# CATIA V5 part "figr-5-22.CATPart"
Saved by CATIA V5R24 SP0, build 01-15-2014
Part number: Part1
Bounding box of the stored display mesh (mm): x -50 to 50, y 0 to 90.129, z 0 to 181.346
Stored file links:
  D:\KAVITA\CATIA V5-6R2014 Project_ Kavita\CATIA V5-6R2014_partfiles\Partfiles\c05_catia_v5-6r2014_prt\figr-5-22.CATPart
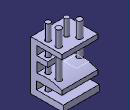
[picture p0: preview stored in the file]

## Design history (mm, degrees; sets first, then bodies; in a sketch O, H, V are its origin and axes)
Set1
  Plane1: type Offset, RefPlane face of Pad1, Offset 44, reversed
  Plane2: type Offset, RefPlane face of Pad1, Offset -46, reversed
Body1 (main body)
  Sketch1 on yz-plane, origin (0, 0, 0), H (0, 1, 0), V (0, 0, 1)
    line L1 (0, 0) -> (90.1292, 0)
    line L2 (90.1292, 0) -> (90.1292, 17.5473)
    line L3 (90.1292, 17.5473) -> (15.9521, 17.5473)
    line L4 (15.9521, 17.5473) -> (15.9521, 39.2532)
    line L5 (15.9521, 39.2532) -> (86.4281, 39.2532)
    line L6 (86.4281, 39.2532) -> (86.4281, 51.1017)
    arc A1 centre (39.4717, -66.63) radius 126.7503 from (86.4281, 51.1017) to (16.1896, 57.9637) ccw
    line L7 (16.1896, 57.9637) -> (16.1896, 86.2043)
    line L8 (16.1896, 86.2043) -> (46.6673, 86.2043)
    line L9 (46.6673, 86.2043) -> (46.6673, 100.2494)
    line L10 (46.6673, 100.2494) -> (16.1896, 100.2494)
    point P12 (16.1896, 100.2494)
    line L11 (16.1896, 100.2494) -> (16.1896, 124.3269)
    line L12 (16.1896, 124.3269) -> (86.4281, 124.3269)
    point P14 (86.4281, 124.3269)
    line L13 (86.4281, 124.3269) -> (86.4281, 137.3459)
    line L14 (86.4281, 137.3459) -> (0, 137.3459)
    point P16 (0, 137.3459)
    line L15 (0, 137.3459) -> (0, 0)
    horizontal: L1 H, L3 H, L5 H, L8 H, L10 H, L12 H, L14 H
    vertical: L2 V, L4 V, L6 V, L7 V, L9 V, L11 V, L13 V, L15 V
    coincidence: P12 L7, P14 L6, P16 V
  Pad1: profile Sketch1, direction (1, 0, 0), length 50, mirrored extent
  Sketch2 on Plane1, origin (0, 0, 181.3459), H (1, 0, 0), V (0, 1, 0)
    circle A1 centre (33.9095, 61.631) radius 7.5057
  Pad2: profile Sketch2, direction (0, 0, -1), up to face of Pad1
  Sketch3 on Plane1, origin (0, 0, 181.3459), H (1, 0, 0), V (0, -1, 0)
    circle A1 centre (-16.2674, -69.1948) radius 7.8522
  Pad3: profile Sketch3, direction (0, 0, -1), up to Plane2
  Sketch4 on Plane1, origin (0, 0, 181.3459), H (1, 0, 0), V (0, -1, 0)
    circle A1 centre (34.469, -32.4508) radius 7.1315
  Pad4: profile Sketch4, direction (0, 0, -1), up to the existing solid (limit type 3)
  Sketch5 on Plane1, origin (0, 0, 181.3459), H (1, 0, 0), V (0, -1, 0)
    circle A1 centre (-3.1833, -46.4863) radius 6.6131
  Pad5: profile Sketch5, direction (0, 0, -1), up to the existing solid (limit type 2)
